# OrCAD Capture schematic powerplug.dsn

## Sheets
1 LOGIC: size A; title: Digital logic; rev: 1
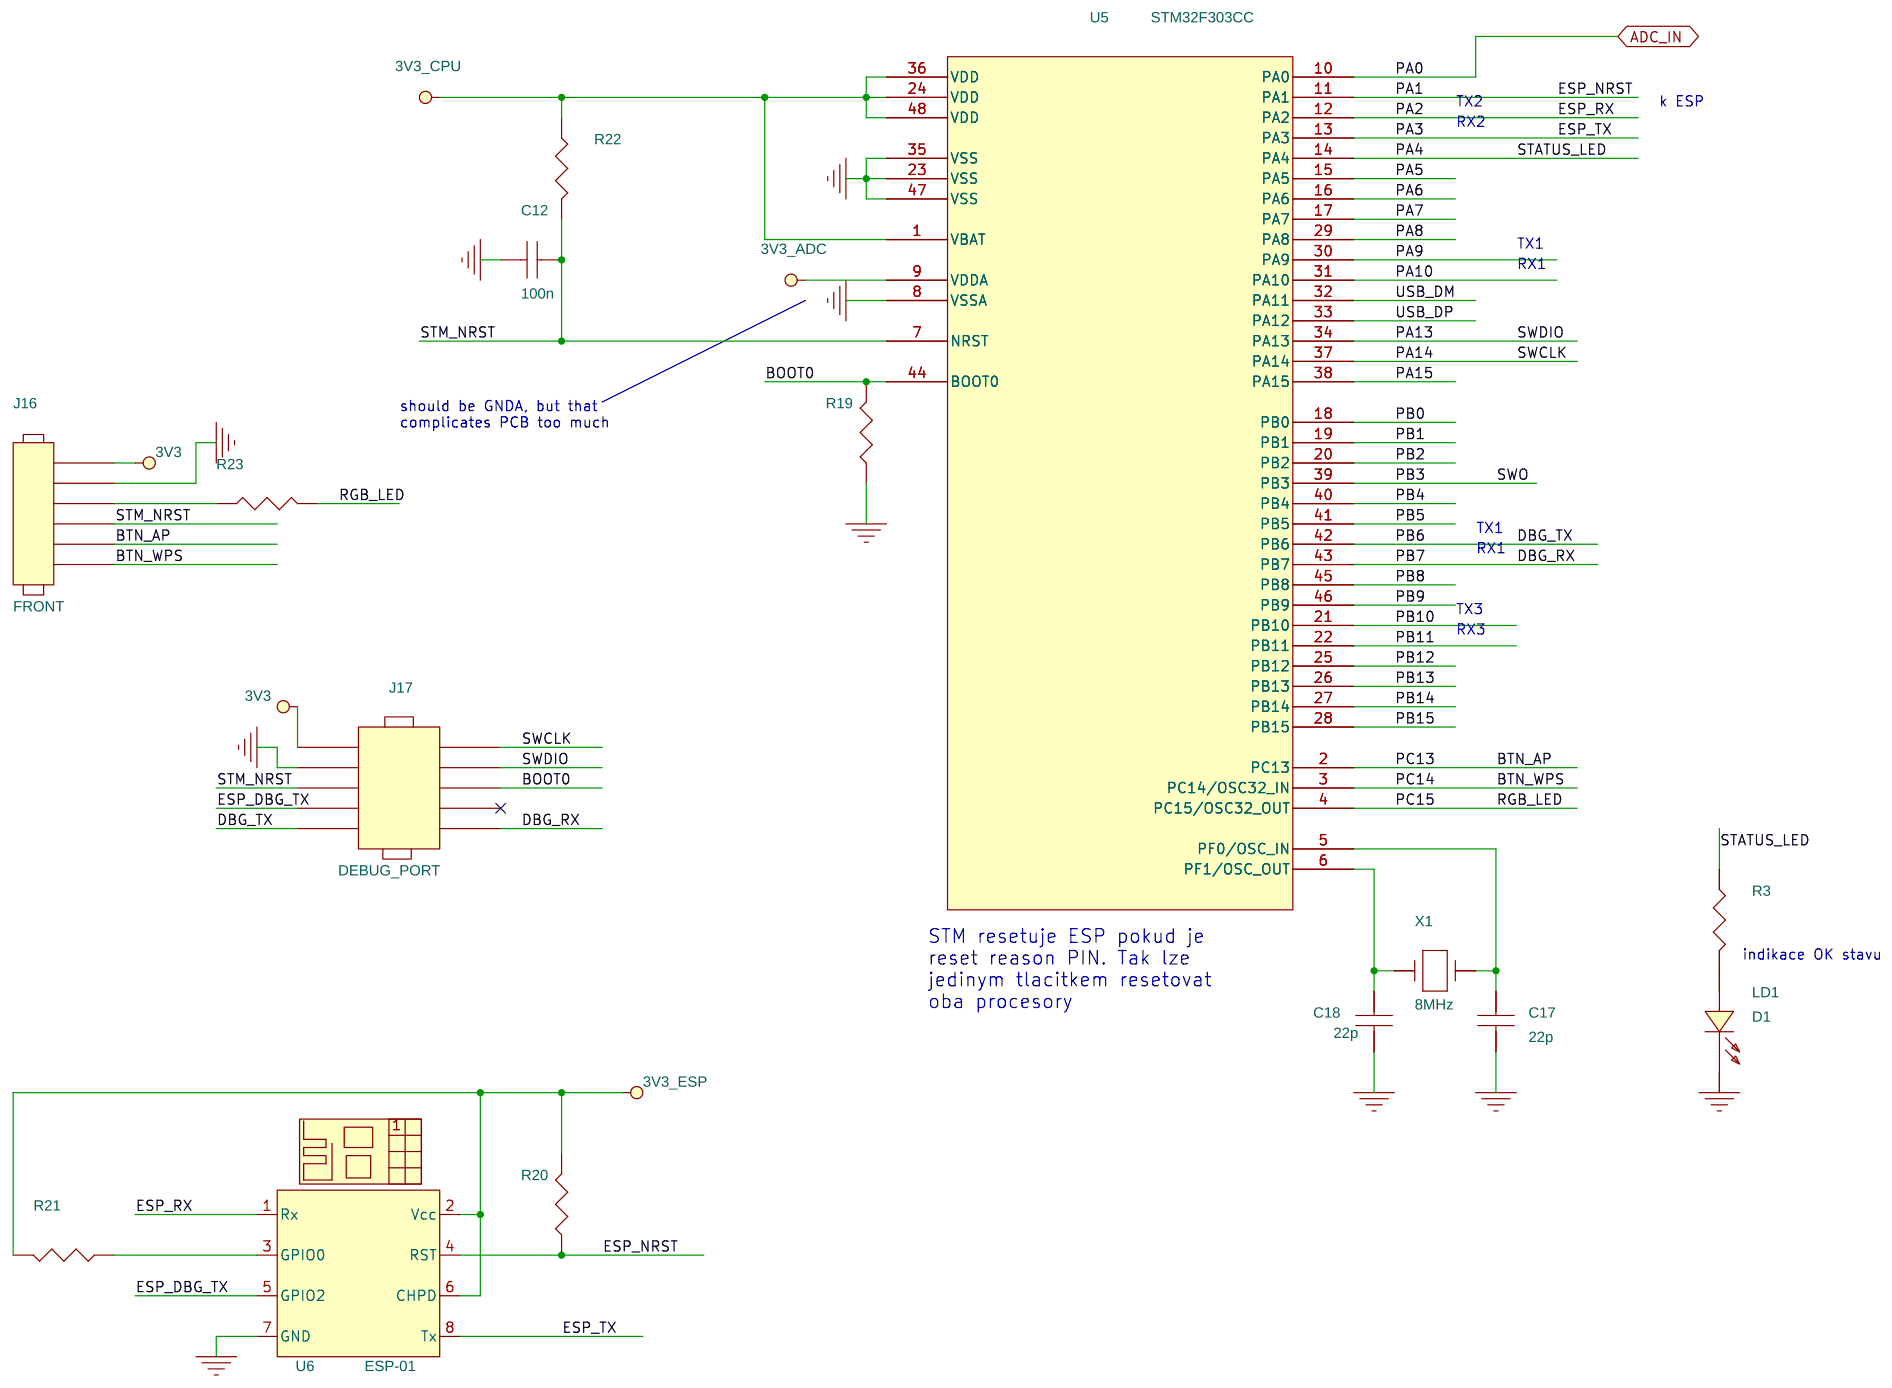
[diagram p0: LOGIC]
2 ANALOG: size A; title: Analog part
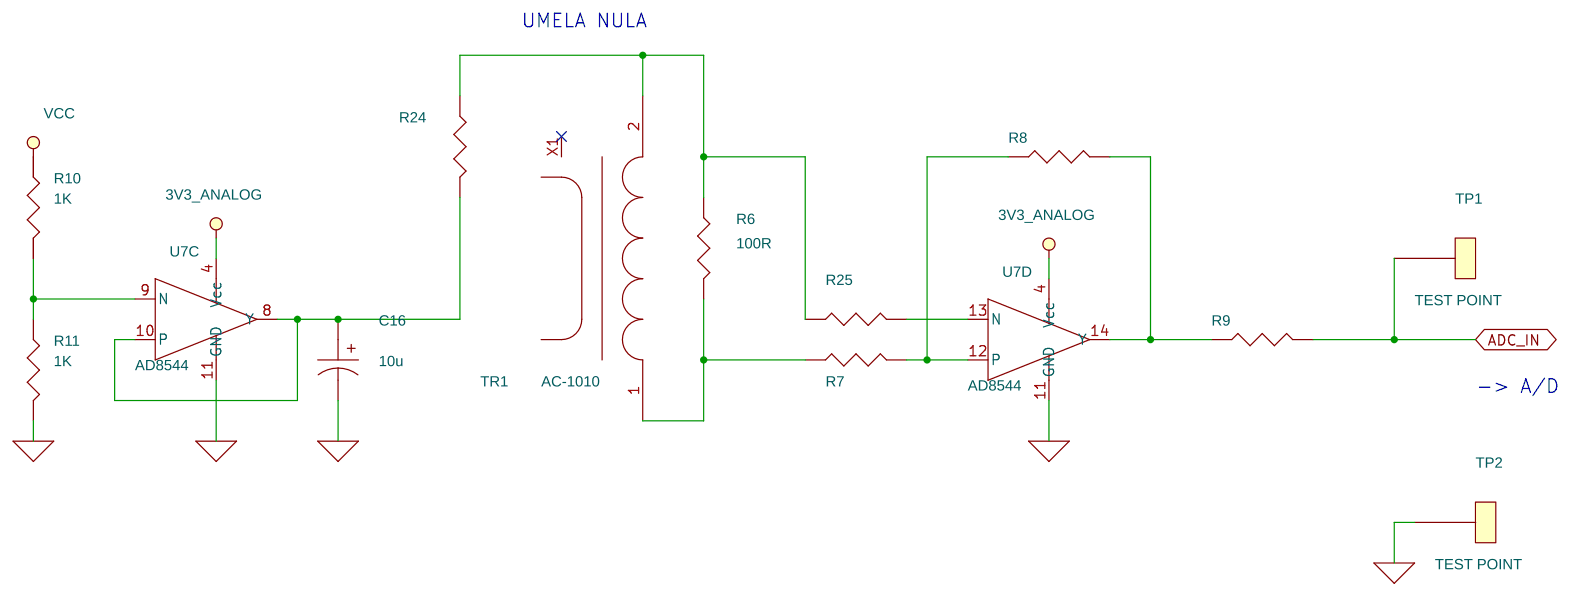
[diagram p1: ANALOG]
3 POWER: size A; title: Power supplies
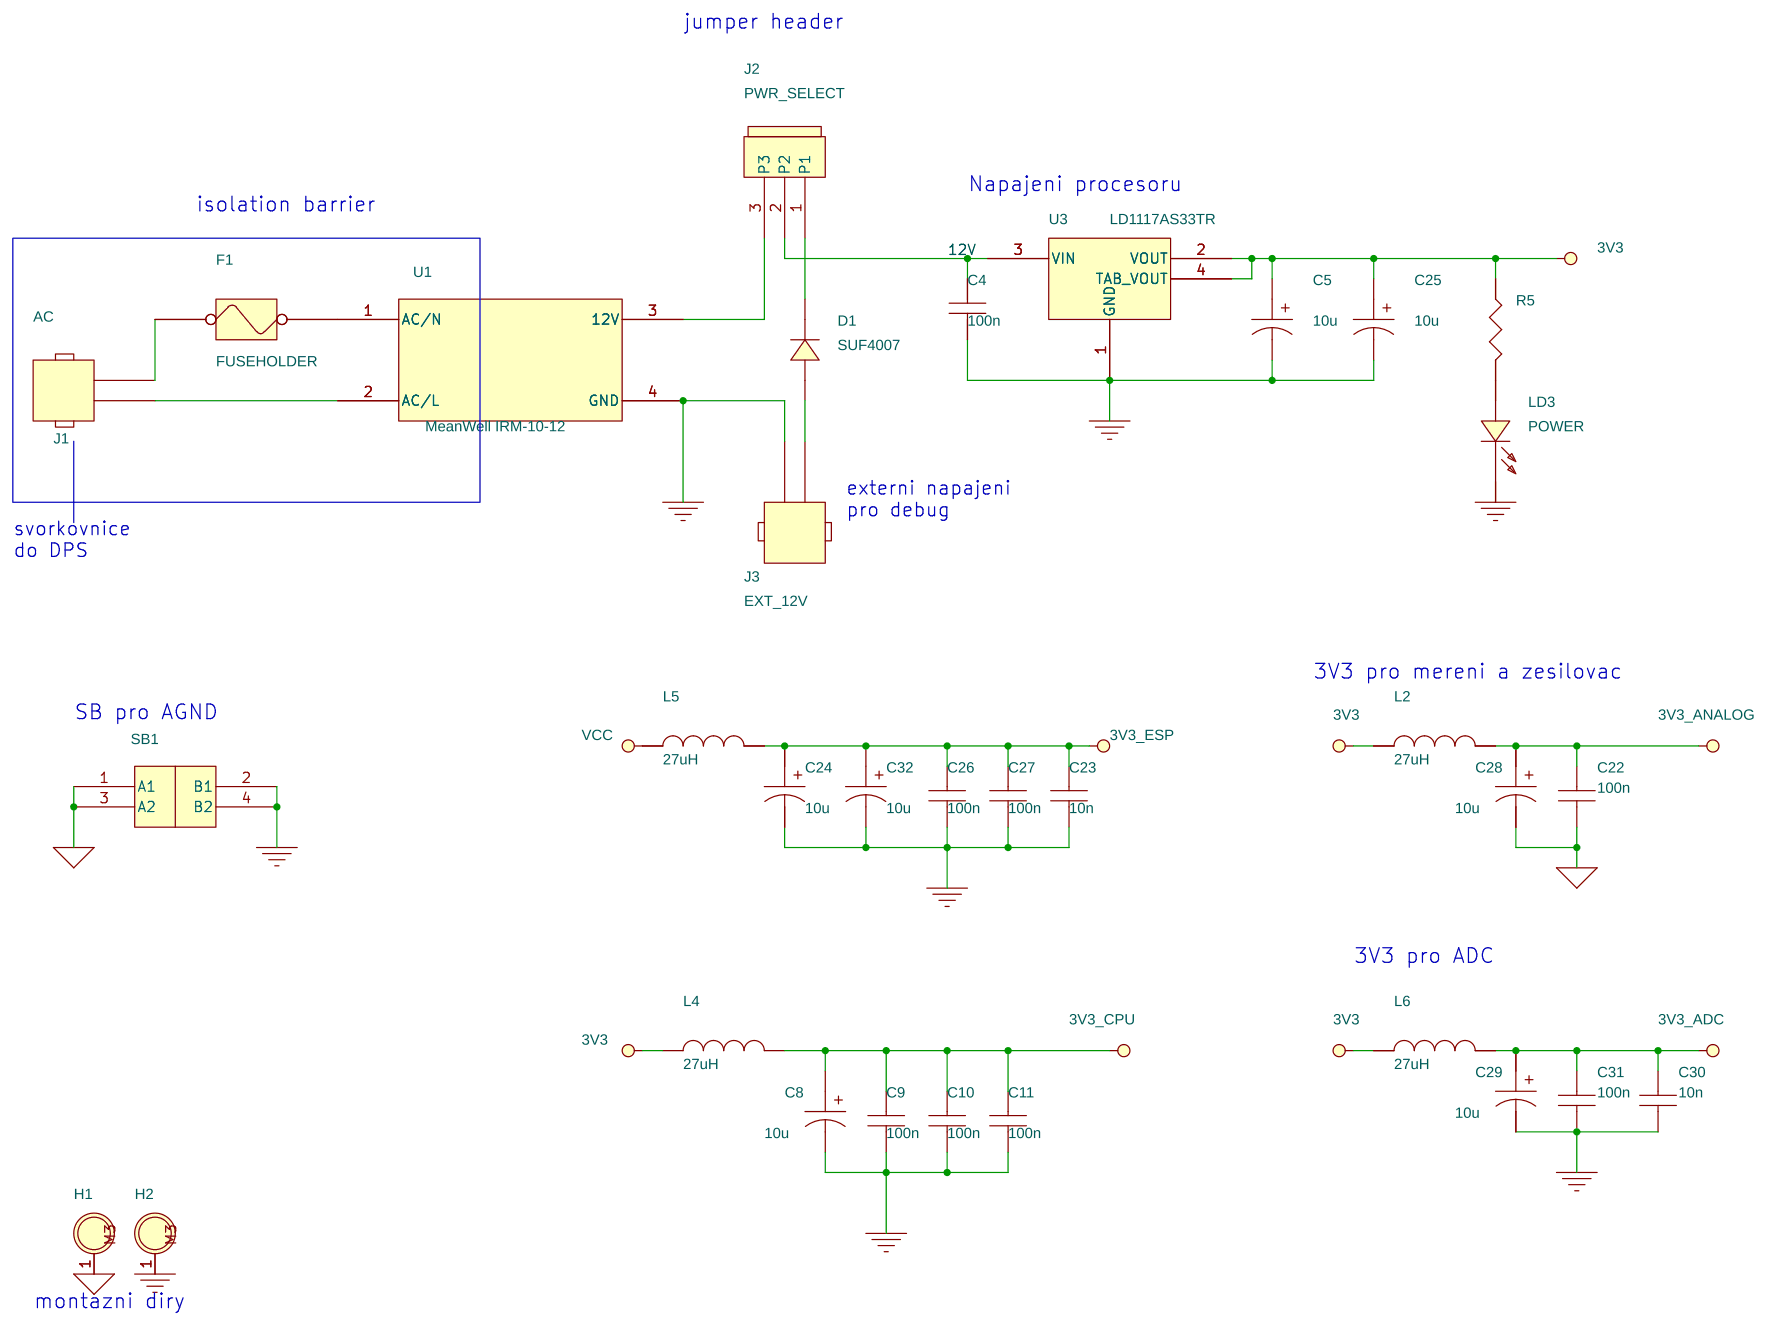
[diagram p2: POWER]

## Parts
sheet ANALOG
C16  10u  [s_1206_cap]
R6  100R  [s_0805]
R7  10k  [s_0805]
R8  100k  [s_0805]
R9  470R  [s_0805]
R10  1K  [s_0805]
R11  1K  [s_0805]
R24  470R  [s_0805]
R25  10k  [s_0805]
TP1  TEST POINT  [t_testpoint]
TP2  TEST POINT  [t_testpoint]
TR1  AC-1010  [t_talema_cur_tr]
U7  AD8544  [s_soic14_n]  (sections C,D)
sheet LOGIC
C12  100n  [s_0805]
C17  22p  [s_0805]
C18  22p  [s_0805]
J16  FRONT  [t_sip6]
J17  DEBUG_PORT  [t_header5x2]
LD1  D1  [s_0805_led]
R3  470  [s_0805]
R19  10k  [s_0805]
R20  100k  [s_0805]
R21  100k  [s_0805]
R22  100k  [s_0805]
R23  470  [s_0805]
U5  STM32F303CC  [s_lqfp48]
U6  ESP-01  [esp01]
X1  8MHz  [t_xtal50]
sheet POWER
C4  100n  [s_0805]
C5  10u  [s_1206_cap]
C8  10u  [s_1206_cap]
C9  100n  [s_0805]
C10  100n  [s_0805]
C11  100n  [s_0805]
C22  100n  [s_0805]
C23  10n  [s_0805]
C24  10u  [s_1206_cap]
C25  10u  [s_1206_cap]
C26  100n  [s_0805]
C27  100n  [s_0805]
C28  10u  [s_1206_cap]
C29  10u  [s_1206_cap]
C30  10n  [s_0805]
C31  100n  [s_0805]
C32  10u  [s_1206_cap]
D1  SUF4007  [s_melf]
F1  FUSEHOLDER  [t_fuse]
H1  MOUNT HOLE M3  [mount_hole_m3]
H2  MOUNT HOLE M3  [mount_hole_m3]
J1  AC  [t_power_con]
J2  PWR_SELECT  [t_sip3]
J3  EXT_12V  [t_sip2]
L2  27uH  [s_1210]
L4  27uH  [s_1210]
L5  27uH  [s_1210]
L6  27uH  [s_1210]
LD3  POWER  [s_0805_led]
R5  150  [s_0805]
SB1  AGND BRIDGE  [t_agnd_bridge]
U1  MeanWell IRM-10-12  [t_meanwell_psu]
U3  LD1117AS33TR  [s_sot223]

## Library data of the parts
C5 C8 C16 C24 C25 C28 C29 C32 = CAP_POL
R3 R5-R11 R19-R25 = RESISTOR
TP1 TP2 = TEST_POINT
TR1 = ac-1010
U7 = AD8544
C4 C9-C12 C17 C18 C22 C23 C26 C27 C30 C31 = CAPACITOR_NON-POL
J16 = HEADER_6
J17 = HEADER_5X2
LD1 LD3 = LED
U5 = stm32f303cct6
U6 = ESP-01
X1 = CRYSTAL
D1 = DIODE
F1 = FUSEHOLDER
H1 H2 = MOUNT_HOLE_M3
J1 J3 = HEADER_2
J2 = JUMPER_3
L2 L4-L6 = INDUCTOR
SB1 = AGND_BRIDGE
U1 = meanwell_psu
U3 = LD1117AS33TR

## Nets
3V3: C5.1 C25.1 J16.1 J17.1 L2.1 L4.1 L5.1 L6.1 R5.1 U3.2(VOUT) U3.4(TAB_VOUT)
3V3_ADC: C29.1 C30.1 C31.1 L6.2 U5.9(VDDA)
3V3_ANALOG: C22.1 C28.1 L2.2 R10.1 U7.4(Vcc)
3V3_CPU: C8.1 C9.1 C10.1 C11.1 L4.2 R22.1 U5.1(VBAT) U5.24(VDD) U5.36(VDD) U5.48(VDD)
3V3_ESP: C23.1 C24.1 C26.1 C27.1 C32.1 L5.2 R20.2 R21.2 U6.2(Vcc) U6.6(CHPD)
12V: C4.1 J2.2(P2) U3.3(VIN)
GND: C4.2 C5.2 C8.2 C9.2 C10.2 C11.2 C12.2 C17.2 C18.2 C23.2 C24.2 C25.2 C26.2 C27.2 C29.2 C30.2 C31.2 C32.2 H2.1 J3.2 J16.2 J17.3 LD1.1(CATHODE) LD3.1(CATHODE) R19.1 SB1.2(B1) SB1.4(B2) U1.4(GND) U3.1(GND) U5.8(VSSA) U5.23(VSS) U5.35(VSS) U5.47(VSS) U6.7(GND)
GNDA: C16.2 C22.2 C28.2 H1.1 R11.2 SB1.1(A1) SB1.3(A2) TP2.1 U7.11(GND)
ADC_IN: R9.2 TP1.1 U5.10(PA0)
BOOT0: J17.6 R19.2 U5.44(BOOT0)
BTN_AP: J16.5 U5.2(PC13)
BTN_WPS: J16.6 U5.3(PC14/OSC32_IN)
DBG_RX: J17.10 U5.43(PB7)
DBG_TX: J17.9 U5.42(PB6)
ESP_DBG_TX: J17.7 U6.5(GPIO2)
ESP_NRST: R20.1 U5.11(PA1) U6.4(RST)
ESP_RX: U5.12(PA2) U6.1(Rx)
ESP_TX: U5.13(PA3) U6.8(Tx)
PA4: R3.1 U5.14(PA4)
PA5: U5.15(PA5)
PA6: U5.16(PA6)
PA7: U5.17(PA7)
PA8: U5.29(PA8)
PA9: U5.30(PA9)
PA10: U5.31(PA10)
PA13: J17.4 U5.34(PA13)
PA14: J17.2 U5.37(PA14)
PA15: U5.38(PA15)
PB0: U5.18(PB0)
PB1: U5.19(PB1)
PB2: U5.20(PB2)
PB3: U5.39(PB3)
PB4: U5.40(PB4)
PB5: U5.41(PB5)
PB8: U5.45(PB8)
PB9: U5.46(PB9)
PB10: U5.21(PB10)
PB11: U5.22(PB11)
PB12: U5.25(PB12)
PB13: U5.26(PB13)
PB14: U5.27(PB14)
PB15: U5.28(PB15)
PC15: R23.2 U5.4(PC15/OSC32_OUT)
STM_NRST: C12.1 J16.4 J17.5 R22.2 U5.7(NRST)
USB_DM: U5.32(PA11)
USB_DP: U5.33(PA12)
N50776: F1.1 J1.2
N50985: J2.3(P3) U1.3(12V)
N125461: R7.2 R8.1 U7.12(P)
N125469: R8.2 R9.1 U7.14(Y)
N125661: R10.2 R11.1 U7.9(N)
N125707: C16.1 R24.2 U7.8(Y) U7.10(P)
N128674: C18.1 U5.6(PF1/OSC_OUT) X1.2
N128682: C17.1 U5.5(PF0/OSC_IN) X1.1
N134498: R21.1 U6.3(GPIO0)
N141672: J16.3 R23.1
N147532: D1.2(A) J3.1
N147956: D1.1(K) J2.1(P1)
N153457: J1.1 U1.2(AC/L)
N158713: R25.2 U7.13(N)
N165035: R6.2 R7.1 TR1.1
N165680: R6.1 R24.1 R25.1 TR1.2
N170733: F1.2 U1.1(AC/N)
N170735: LD3.2(ANODE) R5.2
N171286: LD1.2(ANODE) R3.2

Not connected (* = marked no-connect by the designer): J17 8*; TR1 X1*

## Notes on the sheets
sheet 1
- TX2
- k ESP
- RX2
- TX1
- RX1
- should be GNDA, but that
  complicates PCB too much
- TX1
- RX1
- TX3
- RX3
- STM resetuje ESP pokud je
  reset reason PIN. Tak lze
  jedinym tlacitkem resetovat
  oba procesory
- indikace OK stavu
sheet 2
- UMELA NULA
- -> A/D
sheet 3
- jumper header
- Napajeni procesoru
- isolation barrier
- externi napajeni
  pro debug
- svorkovnice
  do DPS
- 3V3 pro mereni a zesilovac
- SB pro AGND
- 3V3 pro ADC
- montazni diry
